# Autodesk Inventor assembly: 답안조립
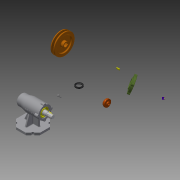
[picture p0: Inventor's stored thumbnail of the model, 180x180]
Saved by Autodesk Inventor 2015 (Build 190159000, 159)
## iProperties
Created: 2019-12
Part Number: 답안조립
Document SubType Name: Assembly
Designer: now
Author: now
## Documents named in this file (12)
- C:\Users\now\Desktop\강민정\491204V1042\답안조립.iam
- C:\Users\now\Desktop\강민정\491204V1042\Ű 5 x 5 x 16.ipt
- C:\Users\now\Desktop\강민정\491204V1042\V벨트풀리.ipt
- C:\Users\now\Desktop\강민정\491204V1042\멈춤나사 M3.ipt
- C:\Users\now\Desktop\강민정\491204V1042\베어링 6004.ipt
- C:\Users\now\Desktop\강민정\491204V1042\베어링 51202.ipt
- C:\Users\now\Desktop\강민정\491204V1042\본체.ipt
- C:\Users\now\Desktop\강민정\491204V1042\볼트 M4.ipt
- C:\Users\now\Desktop\강민정\491204V1042\어댑터슬리브.ipt
- C:\Users\now\Desktop\강민정\491204V1042\오일 실.ipt
- C:\Users\now\Desktop\강민정\491204V1042\축.ipt
- C:\Users\now\Desktop\강민정\491204V1042\커버.ipt
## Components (2 placed, 2 different names)
1. Ű 5 x 5 x 16:1
2. V벨트풀리:1
